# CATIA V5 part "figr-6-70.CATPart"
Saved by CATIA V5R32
Part number: Part1
Bounding box of the stored display mesh (mm): x -44.666 to 106.759, y -69.79 to 69.79, z 0 to 74
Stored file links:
  D:\PROJECTS\Project 2022\CATIA V5 6R 2022\Resources\Part Files\c06_catia_v5_6r2022_prt\figr-6-70.CATPart
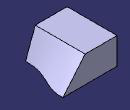
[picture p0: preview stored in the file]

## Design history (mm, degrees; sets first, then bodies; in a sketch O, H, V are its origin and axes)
Body1 (main body)
  Sketch1 on xy-plane, origin (0, 0, 0), H (1, 0, 0), V (0, 1, 0)
    line L1 (44.6658, 69.7903) -> (44.6658, -69.7903)
    line L2 (44.6658, -69.7903) -> (-44.6658, -69.7903)
    line L3 (-44.6658, -69.7903) -> (-44.6658, 69.7903)
    line L4 (-44.6658, 69.7903) -> (44.6658, 69.7903)
    vertical: L1 V, L3 V
    horizontal: L2 H, L4 H
    equidistance: L1 L3 O, L2 L4 O
  Pad1: profile Sketch1, direction (0, 0, 1), length 74
  Draft1: Angle 30, Neutral face of Pad1, PullDir face of Pad1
